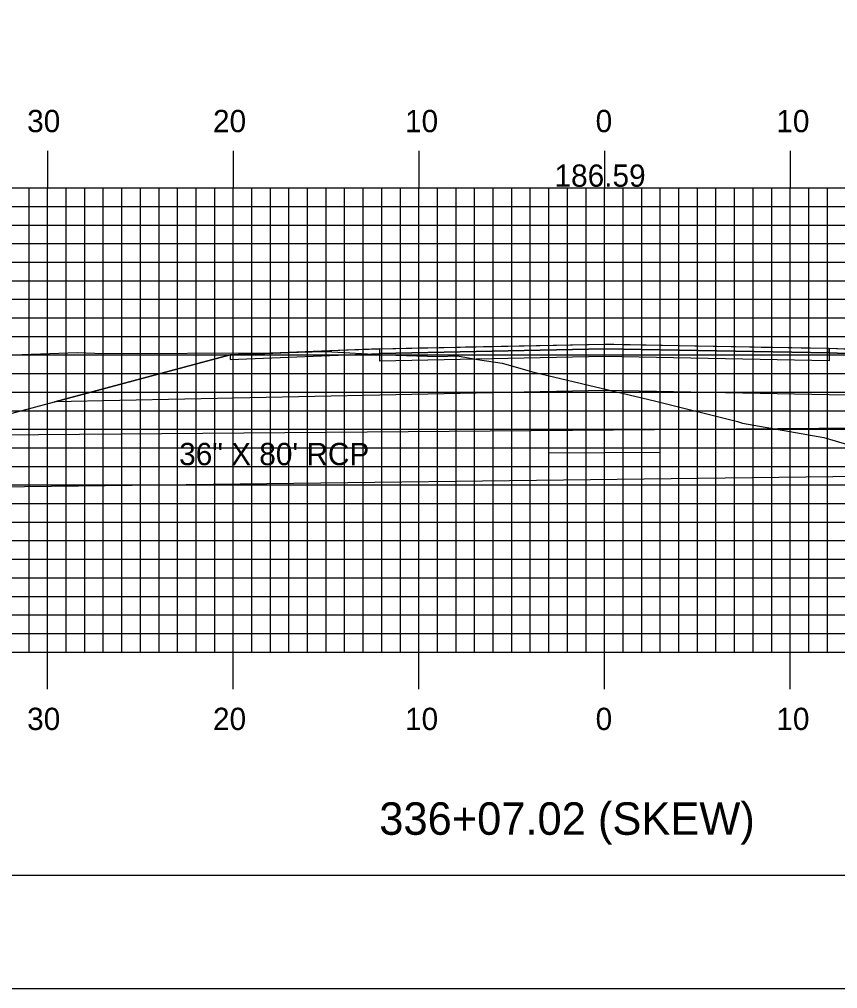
# Model space of a CAD drawing. Extents: x 1823571 to 1823914, y 442310 to 442530.
# Drawn here: x 1823705.4 to 1823749.5, y 442310 to 442362.2 of the extents above; entities that cross this region are included whole.
import ezdxf

# ---------------------------------------------------------------- set-up
doc = ezdxf.new("R2010")
doc.units = 0
for name, color, linetype in [('BORDER', 7, 'Continuous'), ('D_Drainage_Culvert', 7, 'Continuous'), ('D_Drainage_Text', 7, 'Continuous'), ('D_Roadway_Centerline', 7, 'Continuous'), ('D_Roadway_Centerline_Text', 7, 'Continuous'), ('D_Roadway_Edge_Shoulder', 7, 'Continuous'), ('D_Roadway_Edge_TW', 7, 'Continuous'), ('D_Roadway_Pavement', 7, 'Continuous'), ('D_Roadway_SlopeLines', 7, 'Continuous'), ('D_Roadway_SubGrade', 7, 'Continuous'), ('H_V ANNOTATION', 7, 'Continuous'), ('MAJOR', 7, 'Continuous'), ('MINOR', 7, 'Continuous'), ('PLOT BOUNDARY', 7, 'Continuous'), ('S_Roadway_Centerline', 7, 'Continuous')]:
    doc.layers.add(name, color=color, linetype=linetype)

msp = doc.modelspace()

# ---------------------------------------------------------------- linework, layer by layer
at = {"layer": 'BORDER'}
msp.add_lwpolyline([(1823587.3, 442316.105), (1823907.3, 442316.105), (1823907.3, 442526.105), (1823587.3, 442526.105)], close=True, dxfattribs=at)
at = {"layer": 'D_Drainage_Culvert'}
for p, q in [((1823695.626, 442339.755), (1823775.623, 442340.383)), ((1823739.9, 442338.87), (1823733.9, 442338.823)), ((1823775.653, 442337.862), (1823695.648, 442336.899))]:
    msp.add_line(p, q, dxfattribs=at)
at = {"layer": 'D_Roadway_Centerline'}
msp.add_lwpolyline([(1823703.702, 442340.631), (1823716.727, 442344.127), (1823717.927, 442344.175), (1823718.594, 442344.202), (1823720.342, 442344.273), (1823721.761, 442344.33), (1823723.084, 442344.384), (1823724.796, 442344.453), (1823726.907, 442344.497), (1823727.994, 442344.519), (1823728.925, 442344.538), (1823729.407, 442344.548), (1823732.308, 442344.608), (1823736.9, 442344.703), (1823736.994, 442344.701), (1823737.053, 442344.7), (1823737.381, 442344.694), (1823737.395, 442344.694), (1823741.764, 442344.611), (1823744.698, 442344.555), (1823745.334, 442344.543), (1823746.795, 442344.515), (1823747.49, 442344.502), (1823749.004, 442344.473), (1823750.983, 442344.396)], dxfattribs=at)
at = {"layer": 'D_Roadway_Edge_Shoulder'}
for points in [[(1823724.796, 442344.453), (1823716.727, 442344.127), (1823716.727, 442343.877), (1823724.796, 442344.203)], [(1823749.004, 442344.473), (1823757.073, 442344.16), (1823757.073, 442343.91), (1823749.004, 442344.223)]]:
    msp.add_lwpolyline(points, close=True, dxfattribs=at)
at = {"layer": 'D_Roadway_Edge_TW'}
msp.add_lwpolyline([(1823724.796, 442344.203), (1823724.796, 442344.453), (1823736.9, 442344.703), (1823749.004, 442344.473), (1823749.004, 442344.223), (1823736.9, 442344.453)], close=True, dxfattribs=at)
at = {"layer": 'D_Roadway_Pavement'}
msp.add_lwpolyline([(1823724.796, 442343.787), (1823724.796, 442344.203), (1823736.9, 442344.453), (1823749.004, 442344.223), (1823749.004, 442343.806), (1823736.9, 442344.036)], close=True, dxfattribs=at)
at = {"layer": 'D_Roadway_SlopeLines'}
msp.add_line((1823716.727, 442344.127), (1823707.283, 442341.592), dxfattribs=at)
at = {"layer": 'D_Roadway_SubGrade'}
msp.add_lwpolyline([(1823724.796, 442341.953), (1823707.283, 442341.592), (1823716.727, 442344.127), (1823716.727, 442343.877), (1823724.796, 442344.203), (1823736.9, 442344.453), (1823749.004, 442344.223), (1823757.073, 442343.91), (1823757.073, 442344.16), (1823767.336, 442341.625), (1823749.004, 442341.973), (1823736.9, 442342.203)], close=True, dxfattribs=at)
at = {"layer": 'MAJOR'}
for p, q in [((1823706.9, 442355.119), (1823706.9, 442353.115)), ((1823716.9, 442355.119), (1823716.9, 442353.115)), ((1823726.9, 442355.119), (1823726.9, 442353.115)), ((1823736.9, 442355.119), (1823736.9, 442353.115)), ((1823746.9, 442355.119), (1823746.9, 442353.115)), ((1823596.9, 442353.115), (1823876.9, 442353.115)), ((1823706.9, 442328.115), (1823706.9, 442353.115)), ((1823716.9, 442328.115), (1823716.9, 442353.115)), ((1823726.9, 442328.115), (1823726.9, 442353.115)), ((1823736.9, 442328.115), (1823736.9, 442353.115)), ((1823746.9, 442328.115), (1823746.9, 442353.115)), ((1823596.9, 442348.115), (1823876.9, 442348.115)), ((1823596.9, 442343.115), (1823876.9, 442343.115)), ((1823596.9, 442338.115), (1823876.9, 442338.115)), ((1823596.9, 442333.115), (1823876.9, 442333.115)), ((1823596.9, 442328.115), (1823876.9, 442328.115)), ((1823596.9, 442328.115), (1823876.9, 442328.115)), ((1823706.9, 442326.111), (1823706.9, 442328.115)), ((1823716.9, 442326.111), (1823716.9, 442328.115)), ((1823726.9, 442326.111), (1823726.9, 442328.115)), ((1823736.9, 442326.111), (1823736.9, 442328.115)), ((1823746.9, 442326.111), (1823746.9, 442328.115))]:
    msp.add_line(p, q, dxfattribs=at)
at = {"layer": 'MINOR'}
for p, q in [((1823705.9, 442328.115), (1823705.9, 442353.115)), ((1823707.9, 442328.115), (1823707.9, 442353.115)), ((1823708.9, 442328.115), (1823708.9, 442353.115)), ((1823709.9, 442328.115), (1823709.9, 442353.115)), ((1823710.9, 442328.115), (1823710.9, 442353.115)), ((1823711.9, 442328.115), (1823711.9, 442353.115)), ((1823712.9, 442328.115), (1823712.9, 442353.115)), ((1823713.9, 442328.115), (1823713.9, 442353.115)), ((1823714.9, 442328.115), (1823714.9, 442353.115)), ((1823715.9, 442328.115), (1823715.9, 442353.115)), ((1823717.9, 442328.115), (1823717.9, 442353.115)), ((1823718.9, 442328.115), (1823718.9, 442353.115)), ((1823719.9, 442328.115), (1823719.9, 442353.115)), ((1823720.9, 442328.115), (1823720.9, 442353.115)), ((1823721.9, 442328.115), (1823721.9, 442353.115)), ((1823722.9, 442328.115), (1823722.9, 442353.115)), ((1823723.9, 442328.115), (1823723.9, 442353.115)), ((1823724.9, 442328.115), (1823724.9, 442353.115)), ((1823725.9, 442328.115), (1823725.9, 442353.115)), ((1823727.9, 442328.115), (1823727.9, 442353.115)), ((1823728.9, 442328.115), (1823728.9, 442353.115)), ((1823729.9, 442328.115), (1823729.9, 442353.115)), ((1823730.9, 442328.115), (1823730.9, 442353.115)), ((1823731.9, 442328.115), (1823731.9, 442353.115)), ((1823732.9, 442328.115), (1823732.9, 442353.115)), ((1823733.9, 442328.115), (1823733.9, 442353.115)), ((1823734.9, 442328.115), (1823734.9, 442353.115)), ((1823735.9, 442328.115), (1823735.9, 442353.115)), ((1823737.9, 442328.115), (1823737.9, 442353.115)), ((1823738.9, 442328.115), (1823738.9, 442353.115)), ((1823739.9, 442328.115), (1823739.9, 442353.115)), ((1823740.9, 442328.115), (1823740.9, 442353.115)), ((1823741.9, 442328.115), (1823741.9, 442353.115)), ((1823742.9, 442328.115), (1823742.9, 442353.115)), ((1823743.9, 442328.115), (1823743.9, 442353.115)), ((1823744.9, 442328.115), (1823744.9, 442353.115)), ((1823745.9, 442328.115), (1823745.9, 442353.115)), ((1823747.9, 442328.115), (1823747.9, 442353.115)), ((1823748.9, 442328.115), (1823748.9, 442353.115)), ((1823596.9, 442352.115), (1823876.9, 442352.115)), ((1823596.9, 442351.115), (1823876.9, 442351.115)), ((1823596.9, 442350.115), (1823876.9, 442350.115)), ((1823596.9, 442349.115), (1823876.9, 442349.115)), ((1823596.9, 442347.115), (1823876.9, 442347.115)), ((1823596.9, 442346.115), (1823876.9, 442346.115)), ((1823596.9, 442345.115), (1823876.9, 442345.115)), ((1823596.9, 442344.115), (1823876.9, 442344.115)), ((1823596.9, 442342.115), (1823876.9, 442342.115)), ((1823596.9, 442341.115), (1823876.9, 442341.115)), ((1823596.9, 442340.115), (1823876.9, 442340.115)), ((1823596.9, 442339.115), (1823876.9, 442339.115)), ((1823596.9, 442337.115), (1823876.9, 442337.115)), ((1823596.9, 442336.115), (1823876.9, 442336.115)), ((1823596.9, 442335.115), (1823876.9, 442335.115)), ((1823596.9, 442334.115), (1823876.9, 442334.115)), ((1823596.9, 442332.115), (1823876.9, 442332.115)), ((1823596.9, 442331.115), (1823876.9, 442331.115)), ((1823596.9, 442330.115), (1823876.9, 442330.115)), ((1823596.9, 442329.115), (1823876.9, 442329.115))]:
    msp.add_line(p, q, dxfattribs=at)
at = {"layer": 'PLOT BOUNDARY'}
msp.add_lwpolyline([(1823571.113, 442309.987), (1823911.113, 442309.987), (1823911.113, 442529.987), (1823571.113, 442529.987)], close=True, dxfattribs=at)
at = {"layer": 'S_Roadway_Centerline'}
msp.add_lwpolyline([(1823705.023, 442344.116), (1823708.497, 442344.256), (1823709.916, 442344.202), (1823718.936, 442344.228), (1823721.887, 442344.3), (1823725.093, 442344.121), (1823727.921, 442344.028), (1823728.982, 442344.065), (1823730.057, 442343.878), (1823731.378, 442343.678), (1823733.095, 442343.195), (1823739.663, 442341.629), (1823744.057, 442340.53), (1823744.331, 442340.445), (1823748.703, 442339.678), (1823750.118, 442339.264)], dxfattribs=at)

# ---------------------------------------------------------------- texts
at = {"layer": 'D_Drainage_Text'}
msp.add_text('36" X 80\' RCP', height=1.2, dxfattribs=at).set_placement((1823713.985, 442338.18))
at = {"layer": 'D_Roadway_Centerline_Text'}
msp.add_text('186.59', height=1.2, dxfattribs=at).set_placement((1823734.203, 442353.175))
at = {"layer": 'H_V ANNOTATION'}
for s, height, p in [('30', 1.2, (1823705.797, 442356.115)), ('20', 1.2, (1823715.808, 442356.115)), ('10', 1.2, (1823726.151, 442356.115)), ('0', 1.2, (1823736.418, 442356.115)), ('10', 1.2, (1823746.151, 442356.115)), ('30', 1.2, (1823705.797, 442323.915)), ('20', 1.2, (1823715.808, 442323.915)), ('10', 1.2, (1823726.151, 442323.915)), ('0', 1.2, (1823736.418, 442323.915)), ('10', 1.2, (1823746.151, 442323.915)), ('336+07.02 (SKEW)', 1.74996, (1823724.765, 442318.271))]:
    msp.add_text(s, height=height, dxfattribs=at).set_placement(p)

doc.saveas('drawing.dxf')
